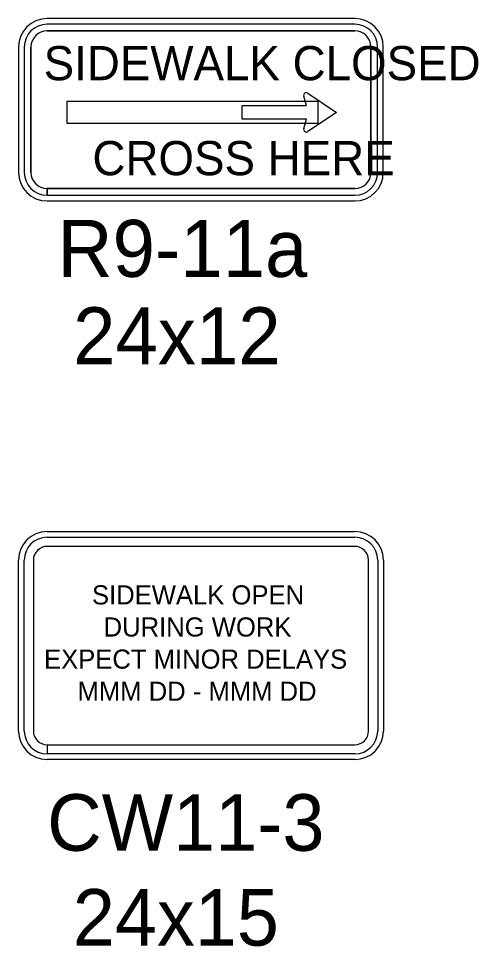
# Model space of a CAD drawing. Extents: x 1458 to 4498, y 17709 to 24109.
# Drawn here: x 2324.1 to 2445.1, y 20688.5 to 20932.7 of the extents above; entities that cross this region are included whole.
import ezdxf

# ---------------------------------------------------------------- set-up
doc = ezdxf.new("R2010")
doc.units = 0
doc.layers.add('P_TRAF_TCP_General', color=7, linetype='Continuous')

msp = doc.modelspace()

# ---------------------------------------------------------------- linework, layer by layer
at = {"layer": 'P_TRAF_TCP_General'}
for p, q in [((2412.59, 20932.69), (2331.62, 20932.69)), ((2412.59, 20931.19), (2331.62, 20931.19)), ((2412.59, 20931.19), (2331.62, 20931.19)), ((2412.59, 20929.44), (2331.62, 20929.44)), ((2331.62, 20929.44), (2412.59, 20929.44)), ((2324.12, 20925.19), (2324.12, 20892.2)), ((2325.62, 20925.19), (2325.62, 20892.2)), ((2325.62, 20925.19), (2325.62, 20892.2)), ((2327.37, 20925.19), (2327.37, 20892.2)), ((2327.37, 20892.2), (2327.37, 20925.19)), ((2416.83, 20892.2), (2416.83, 20925.19)), ((2416.83, 20925.19), (2416.83, 20892.2)), ((2418.58, 20892.2), (2418.58, 20925.19)), ((2418.58, 20892.2), (2418.58, 20925.19)), ((2420.08, 20892.2), (2420.08, 20925.19)), ((2400.26, 20913.08), (2407.75, 20908.01)), ((2399.87, 20909.81), (2399.16, 20912.28)), ((2382.97, 20909.81), (2399.87, 20909.81)), ((2382.97, 20906.21), (2382.97, 20909.81)), ((2399.87, 20906.21), (2382.97, 20906.21)), ((2399.16, 20903.75), (2399.87, 20906.21)), ((2407.75, 20908.01), (2400.25, 20902.93)), ((2331.62, 20887.96), (2412.59, 20887.96)), ((2331.62, 20886.21), (2331.62, 20887.96)), ((2331.62, 20886.21), (2412.59, 20886.21)), ((2412.59, 20887.96), (2331.64, 20887.96)), ((2331.64, 20887.96), (2331.64, 20886.21)), ((2331.64, 20886.21), (2412.59, 20886.21)), ((2331.62, 20884.71), (2412.59, 20884.71)), ((2331.61, 20797.72), (2412.61, 20797.72)), ((2331.61, 20796.22), (2412.61, 20796.22)), ((2412.61, 20793.82), (2331.61, 20793.82)), ((2324.11, 20745.22), (2324.11, 20790.22)), ((2325.61, 20745.22), (2325.61, 20790.22)), ((2328.01, 20790.22), (2328.01, 20745.22)), ((2416.21, 20745.22), (2416.21, 20790.22)), ((2418.61, 20790.22), (2418.61, 20745.22)), ((2420.11, 20790.22), (2420.11, 20745.22)), ((2331.61, 20741.62), (2331.61, 20739.22)), ((2331.61, 20741.62), (2412.61, 20741.62)), ((2412.61, 20739.22), (2331.61, 20739.22)), ((2412.61, 20737.72), (2331.61, 20737.72))]:
    msp.add_line(p, q, dxfattribs=at)
for points in [[(2402.94, 20910.84), (2336.82, 20910.84), (2336.82, 20905.15), (2402.94, 20905.15)], [(2395.08, 20905.15), (2395.08, 20905.15), (2395.08, 20905.15), (2395.08, 20905.15)]]:
    msp.add_lwpolyline(points, close=True, dxfattribs=at)
for centre, radius, start, end in [((2331.62, 20925.19), 7.5, 90, 180), ((2412.59, 20925.19), 7.5, 0, 90), ((2331.62, 20925.19), 6, 90, 180), ((2331.62, 20925.19), 6, 90, 180), ((2412.59, 20925.19), 6, 0, 90), ((2412.59, 20925.19), 6, 0, 90), ((2331.62, 20925.19), 4.25, 90, 180), ((2331.62, 20925.19), 4.25, 90, 180), ((2412.59, 20925.19), 4.25, 0, 90), ((2412.59, 20925.19), 4.25, 0, 90), ((2399.85, 20912.48), 0.724, 55.884, 196.1777), ((2399.85, 20903.54), 0.724, 162.5706, 303.37), ((2331.62, 20892.2), 7.5, 180, 270), ((2331.62, 20892.2), 6, 180, 270), ((2331.62, 20892.2), 6, 180, 270), ((2331.62, 20892.2), 4.25, 180, 270), ((2331.62, 20892.2), 4.25, 180, 270), ((2412.59, 20892.2), 6, 270, 0), ((2412.59, 20892.2), 4.25, 270, 0), ((2412.59, 20892.2), 6, 270, 0), ((2412.59, 20892.2), 4.25, 270, 0), ((2412.59, 20892.2), 7.5, 270, 0), ((2331.61, 20790.22), 7.5, 90, 180), ((2331.61, 20790.22), 6, 90, 180), ((2412.61, 20790.22), 7.5, 0, 90), ((2412.61, 20790.22), 6, 0, 90), ((2331.61, 20790.22), 3.6, 90, 180), ((2412.61, 20790.22), 3.6, 0, 90), ((2331.61, 20745.22), 7.5, 180, 270), ((2331.61, 20745.22), 6, 180, 270), ((2331.61, 20745.22), 3.6, 180, 270), ((2412.61, 20745.22), 7.5, 270, 0), ((2412.61, 20745.22), 6, 270, 0), ((2412.61, 20745.22), 3.6, 270, 0)]:
    msp.add_arc(centre, radius, start, end, dxfattribs=at)

# ---------------------------------------------------------------- texts
for s, height, p in [('SIDEWALK CLOSED', 8.9964, (2330.71, 20916.46)), ('CROSS HERE', 8.996, (2343.55, 20891.47)), ('R9-11a', 14.994, (2334.37, 20864.71)), ('24x12', 14.994, (2338.46, 20841.72)), ('SIDEWALK OPEN', 5.04, (2343.44, 20778.53)), ('DURING WORK', 5.04, (2346.5, 20770.08)), ('EXPECT MINOR DELAYS', 5.04, (2330.82, 20761.63)), ('MMM DD - MMM DD', 5.04, (2339.64, 20753.18)), ('CW11-3', 14.88, (2331.63, 20713.72)), ('24x15', 14.88, (2338.4, 20688.76))]:
    msp.add_text(s, height=height, dxfattribs=at).set_placement(p)

doc.saveas('drawing.dxf')
